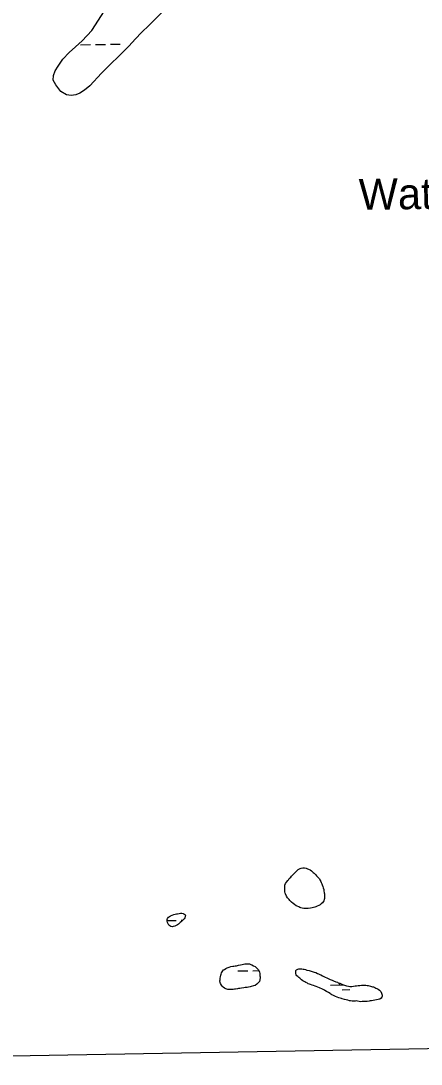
# Model space of a CAD drawing. Extents: x 3903937 to 3942190, y 260677 to 286651.
# Drawn here: x 3909700 to 3910990, y 266016 to 269379 of the extents above; entities that cross this region are included whole.
import ezdxf

# ---------------------------------------------------------------- set-up
doc = ezdxf.new("R2010")
doc.units = 0
for name, color, linetype in [('V-GRID-FRAM', 7, 'Continuous'), ('V-RIVR-IDEN', 7, 'Continuous'), ('V-WETL-SWMP', 7, 'Continuous')]:
    doc.layers.add(name, color=color, linetype=linetype)

msp = doc.modelspace()

# ---------------------------------------------------------------- linework, layer by layer
at = {"layer": 'V-GRID-FRAM'}
msp.add_lwpolyline([(3907892.2, 284196.1), (3939773.2, 284757.2), (3940101.1, 266577.6), (3908204.3, 266016.2), (3907892.2, 284196.1)], dxfattribs=at)
at = {"layer": 'V-WETL-SWMP'}
for p, q in [((3909892.8, 269302.1), (3909924.8, 269302.7)), ((3909940.8, 269302.9), (3909972.8, 269303.5)), ((3909988.8, 269303.8), (3910020.8, 269304.3)), ((3910171.8, 266479), (3910200.4, 266479.5)), ((3910216.4, 266479.8), (3910221.5, 266479.9)), ((3910399.3, 266316.5), (3910431.3, 266317)), ((3910447.3, 266317.3), (3910467.5, 266317.7)), ((3910697.5, 266271), (3910741.2, 266271.7)), ((3910735.8, 266256.2), (3910759.8, 266256.6))]:
    msp.add_line(p, q, dxfattribs=at)
for points in [[(3910172.4, 269424.9), (3910114.1, 269365.6), (3910089, 269341.4), (3910069.6, 269321.4), (3910048.4, 269298), (3910016.2, 269265.9), (3909989.6, 269239.1), (3909960.6, 269210.9), (3909922.2, 269169.9), (3909905.9, 269155.4), (3909889.9, 269145.9), (3909877.5, 269141), (3909862.2, 269138.5), (3909847.1, 269140.7), (3909829.6, 269151.6), (3909812.6, 269173.3), (3909804.7, 269187.9), (3909805.5, 269202.8), (3909810.4, 269217.7), (3909820.4, 269233.4), (3909835.6, 269255.8), (3909855.6, 269277.7), (3909876.2, 269295.7), (3909897.9, 269314.5), (3909928.7, 269347.8), (3909969.7, 269412)], [(3910780.3, 266219.8), (3910777.2, 266219.2), (3910771.8, 266218.9), (3910768.1, 266219.3), (3910762.7, 266219.9), (3910759.2, 266220.7), (3910753.6, 266221.9), (3910748.8, 266223.3), (3910742.8, 266224.8), (3910735.8, 266226.4), (3910732.9, 266227.4), (3910728.8, 266228.6), (3910725.1, 266230), (3910719.3, 266231.9), (3910713.7, 266234.7), (3910707.7, 266237.2), (3910702.7, 266239.8), (3910699.2, 266241.9), (3910696.5, 266243.5), (3910691.3, 266246.6), (3910685.5, 266249.9), (3910679.9, 266253.5), (3910676.4, 266255.6), (3910670.4, 266258.5), (3910664.8, 266260.7), (3910662.1, 266262.3), (3910657.5, 266264.2), (3910652.2, 266266.2), (3910648.6, 266267.4), (3910643, 266269.5), (3910639.1, 266270.7), (3910633.7, 266272.5), (3910630.6, 266273.7), (3910626.3, 266275.4), (3910623.6, 266276.8), (3910618.6, 266279.6), (3910614.9, 266281.5), (3910609.3, 266284.6), (3910604.5, 266288.2), (3910598.9, 266292.8), (3910596.2, 266295.4), (3910592.5, 266299.1), (3910590, 266301.2), (3910587.5, 266304.3), (3910586, 266308.2), (3910586, 266314), (3910586.6, 266318.1), (3910588.9, 266320), (3910593.2, 266321.9), (3910596.3, 266322.9), (3910599.6, 266323.1), (3910605.2, 266323.2), (3910609.5, 266322.4), (3910612.8, 266321.8), (3910616.9, 266320.9), (3910622.1, 266319.5), (3910629, 266317.5), (3910632, 266316.7), (3910638.7, 266315.1), (3910645.1, 266313), (3910650.5, 266311.2), (3910656.1, 266308.8), (3910658.9, 266307.5), (3910663.5, 266305.1), (3910666.6, 266303.7), (3910672.6, 266300.6), (3910676.8, 266298.6), (3910680.9, 266296.5), (3910686.3, 266294.1), (3910690.6, 266292.2), (3910697.3, 266289.2), (3910703.3, 266286.7), (3910709.7, 266283.7), (3910712.6, 266282.8), (3910715.5, 266281.6), (3910720.2, 266280), (3910723.1, 266278.6), (3910727.5, 266277.1), (3910734.1, 266274.3), (3910740.1, 266272.1), (3910746.1, 266270), (3910750, 266268.8), (3910755.8, 266267.2), (3910760.2, 266266.4), (3910767.2, 266266.8), (3910771.9, 266267.5), (3910777.5, 266268.3), (3910781.9, 266268.8), (3910787, 266269.2), (3910792.2, 266269.7), (3910798.2, 266270.7), (3910803.3, 266271), (3910806.8, 266271.2), (3910811.4, 266271.2), (3910816.3, 266270.2), (3910819.7, 266269.4), (3910826.3, 266267.6), (3910833.3, 266265.9), (3910836.4, 266264.9), (3910841.2, 266262.9), (3910844.5, 266261.3)], [(3910844.5, 266261.3), (3910847.6, 266259.8), (3910851.5, 266257.8), (3910856.3, 266254.3), (3910859.8, 266250.8), (3910862.5, 266245.5), (3910864, 266238.9), (3910864.4, 266235.7), (3910863.7, 266232), (3910861.2, 266228.9), (3910856.4, 266225.8), (3910851.5, 266224.5), (3910846.6, 266223.1), (3910841, 266222.2), (3910835.2, 266221.3), (3910829.6, 266220.7), (3910825.5, 266220), (3910822.4, 266219.6), (3910816.2, 266218.6), (3910810.4, 266218.3), (3910806.9, 266217.9), (3910800.3, 266217.6), (3910795.1, 266217.4), (3910780.3, 266219.8)]]:
    msp.add_lwpolyline(points, dxfattribs=at)
for points in [[(3910651, 266523.1), (3910647.4, 266522.3), (3910643.7, 266521.4), (3910639.4, 266520.4), (3910633, 266519.3), (3910626.2, 266518.3), (3910619.8, 266518), (3910612.2, 266518.4), (3910606.2, 266519.4), (3910602.9, 266520.2), (3910599.5, 266521.6), (3910595.8, 266523), (3910590.8, 266525.3), (3910587.5, 266526.9), (3910582.5, 266530.4), (3910577.2, 266534.3), (3910572.4, 266538.6), (3910570.3, 266540.7), (3910567.2, 266543.8), (3910564.7, 266546.4), (3910562.4, 266548.7), (3910559.5, 266552.2), (3910555.8, 266558.1), (3910553, 266564.8), (3910552, 266567.8), (3910551.3, 266572), (3910551.1, 266575.1), (3910550.5, 266579.4), (3910550.4, 266584.6), (3910550.4, 266587.7), (3910551.2, 266593), (3910553.5, 266598.6), (3910556.3, 266603.2), (3910560.6, 266608.2), (3910562.5, 266610.7), (3910565.2, 266614.2), (3910570.1, 266619.4), (3910572.3, 266621.7), (3910575.4, 266625.2), (3910578.7, 266628.7), (3910582.8, 266633.3), (3910584.9, 266635.4), (3910588, 266638.3), (3910593.7, 266643.2), (3910599.7, 266647), (3910603.6, 266648.3), (3910609, 266649.1), (3910613.9, 266648.7), (3910619.5, 266647.5), (3910624.3, 266645.7), (3910627.4, 266644.5), (3910632.1, 266642.2), (3910636.9, 266639.1), (3910642.3, 266634.4), (3910645, 266631.6), (3910649.6, 266627.2), (3910653.1, 266623.3), (3910655.2, 266621.1), (3910658.5, 266617.6), (3910662, 266613.1), (3910663.9, 266610.2), (3910666.8, 266605), (3910668.3, 266602.1), (3910670.2, 266597.4), (3910671.4, 266594.1), (3910672.9, 266588.9), (3910674.4, 266585), (3910676.1, 266578.6), (3910676.9, 266574.7), (3910678, 266568.9), (3910678.8, 266565.2), (3910679, 266561.9), (3910678.9, 266557.6), (3910678.3, 266550.4), (3910677.5, 266547.3), (3910676, 266542.7), (3910674, 266539.4), (3910671.7, 266536.1), (3910668.1, 266532.9), (3910664.6, 266530.2)], [(3910229, 266488), (3910226.7, 266485.1), (3910223.6, 266481.6), (3910219.9, 266478.5), (3910217.5, 266476.4), (3910214, 266473), (3910211.7, 266471), (3910208.2, 266467.9), (3910205.1, 266465.6), (3910200.8, 266463.5), (3910196, 266461.2), (3910191.3, 266459.5), (3910187.4, 266458.8), (3910183.3, 266459.5), (3910179.9, 266461.5), (3910177.6, 266463.8), (3910174.5, 266468.5), (3910172.7, 266472.8), (3910171.8, 266477.4), (3910171.8, 266482.1), (3910173.2, 266485.8), (3910176.5, 266489.6), (3910178.9, 266491.9), (3910182.6, 266494.2), (3910187.8, 266496.5), (3910192.8, 266498.1), (3910197.5, 266499.2), (3910201.8, 266500.4), (3910205.1, 266501.1), (3910210.3, 266501.9), (3910214.4, 266502.4), (3910219.4, 266502.4), (3910222.9, 266501.6), (3910225.8, 266500.6), (3910228.7, 266498.1), (3910230.8, 266495.9)], [(3910469.7, 266282.6), (3910461.1, 266274.2), (3910455.1, 266270.1), (3910449.5, 266268.2), (3910442.9, 266266.5), (3910439.4, 266265.7), (3910434, 266264.6), (3910429.3, 266263.7), (3910423.1, 266262.7), (3910419, 266262.4), (3910411.3, 266261.4), (3910405.6, 266260.5), (3910401.8, 266259.7), (3910397.9, 266259.2), (3910392.2, 266258.2), (3910388.8, 266257.9), (3910383.9, 266257.3), (3910380.4, 266256.7), (3910376.2, 266256.4), (3910370.9, 266256.4), (3910367, 266257), (3910360.5, 266259), (3910356, 266260.9), (3910352.3, 266263.9), (3910348.9, 266267.4), (3910346.8, 266270.3), (3910343.9, 266276.5), (3910342.9, 266279.4), (3910341.8, 266284.7), (3910342, 266287.8), (3910342.4, 266293), (3910343.4, 266297.8), (3910344.8, 266302.9), (3910345.6, 266305.8), (3910346.8, 266310), (3910348.5, 266313.7), (3910350.7, 266317.4), (3910353.4, 266320.1), (3910356.1, 266321.6), (3910361, 266324.5), (3910365.3, 266326.8), (3910368.6, 266327.9), (3910371.7, 266328.7), (3910377.1, 266330.4), (3910383.5, 266331.7), (3910386.8, 266332.1), (3910391.3, 266332.9), (3910395, 266333.6), (3910401.4, 266334.8), (3910407.8, 266335.9), (3910413.6, 266337.2), (3910418.2, 266338.3), (3910421.7, 266339.1), (3910427.4, 266339.7), (3910432, 266339.4), (3910437.1, 266339), (3910441.7, 266337.3), (3910445, 266336.1), (3910450.4, 266333.3), (3910455, 266330.4), (3910459.7, 266326.7), (3910462, 266324.4), (3910465.6, 266320.5), (3910467.6, 266317.5), (3910469.3, 266312.5), (3910469.9, 266308.4), (3910470.2, 266305.1), (3910470.8, 266300.9), (3910471, 266297.6), (3910471.1, 266294.3)]]:
    msp.add_lwpolyline(points, close=True, dxfattribs=at)
msp.add_arc((3910692.3, 266271.3), 35.2, 0.2366, 9.6238, dxfattribs=at)

# ---------------------------------------------------------------- texts
at = {"layer": 'V-RIVR-IDEN'}
msp.add_text('Water', height=100, rotation=0.8107, dxfattribs=at).set_placement((3910789.7, 268769.7))

doc.saveas('drawing.dxf')
